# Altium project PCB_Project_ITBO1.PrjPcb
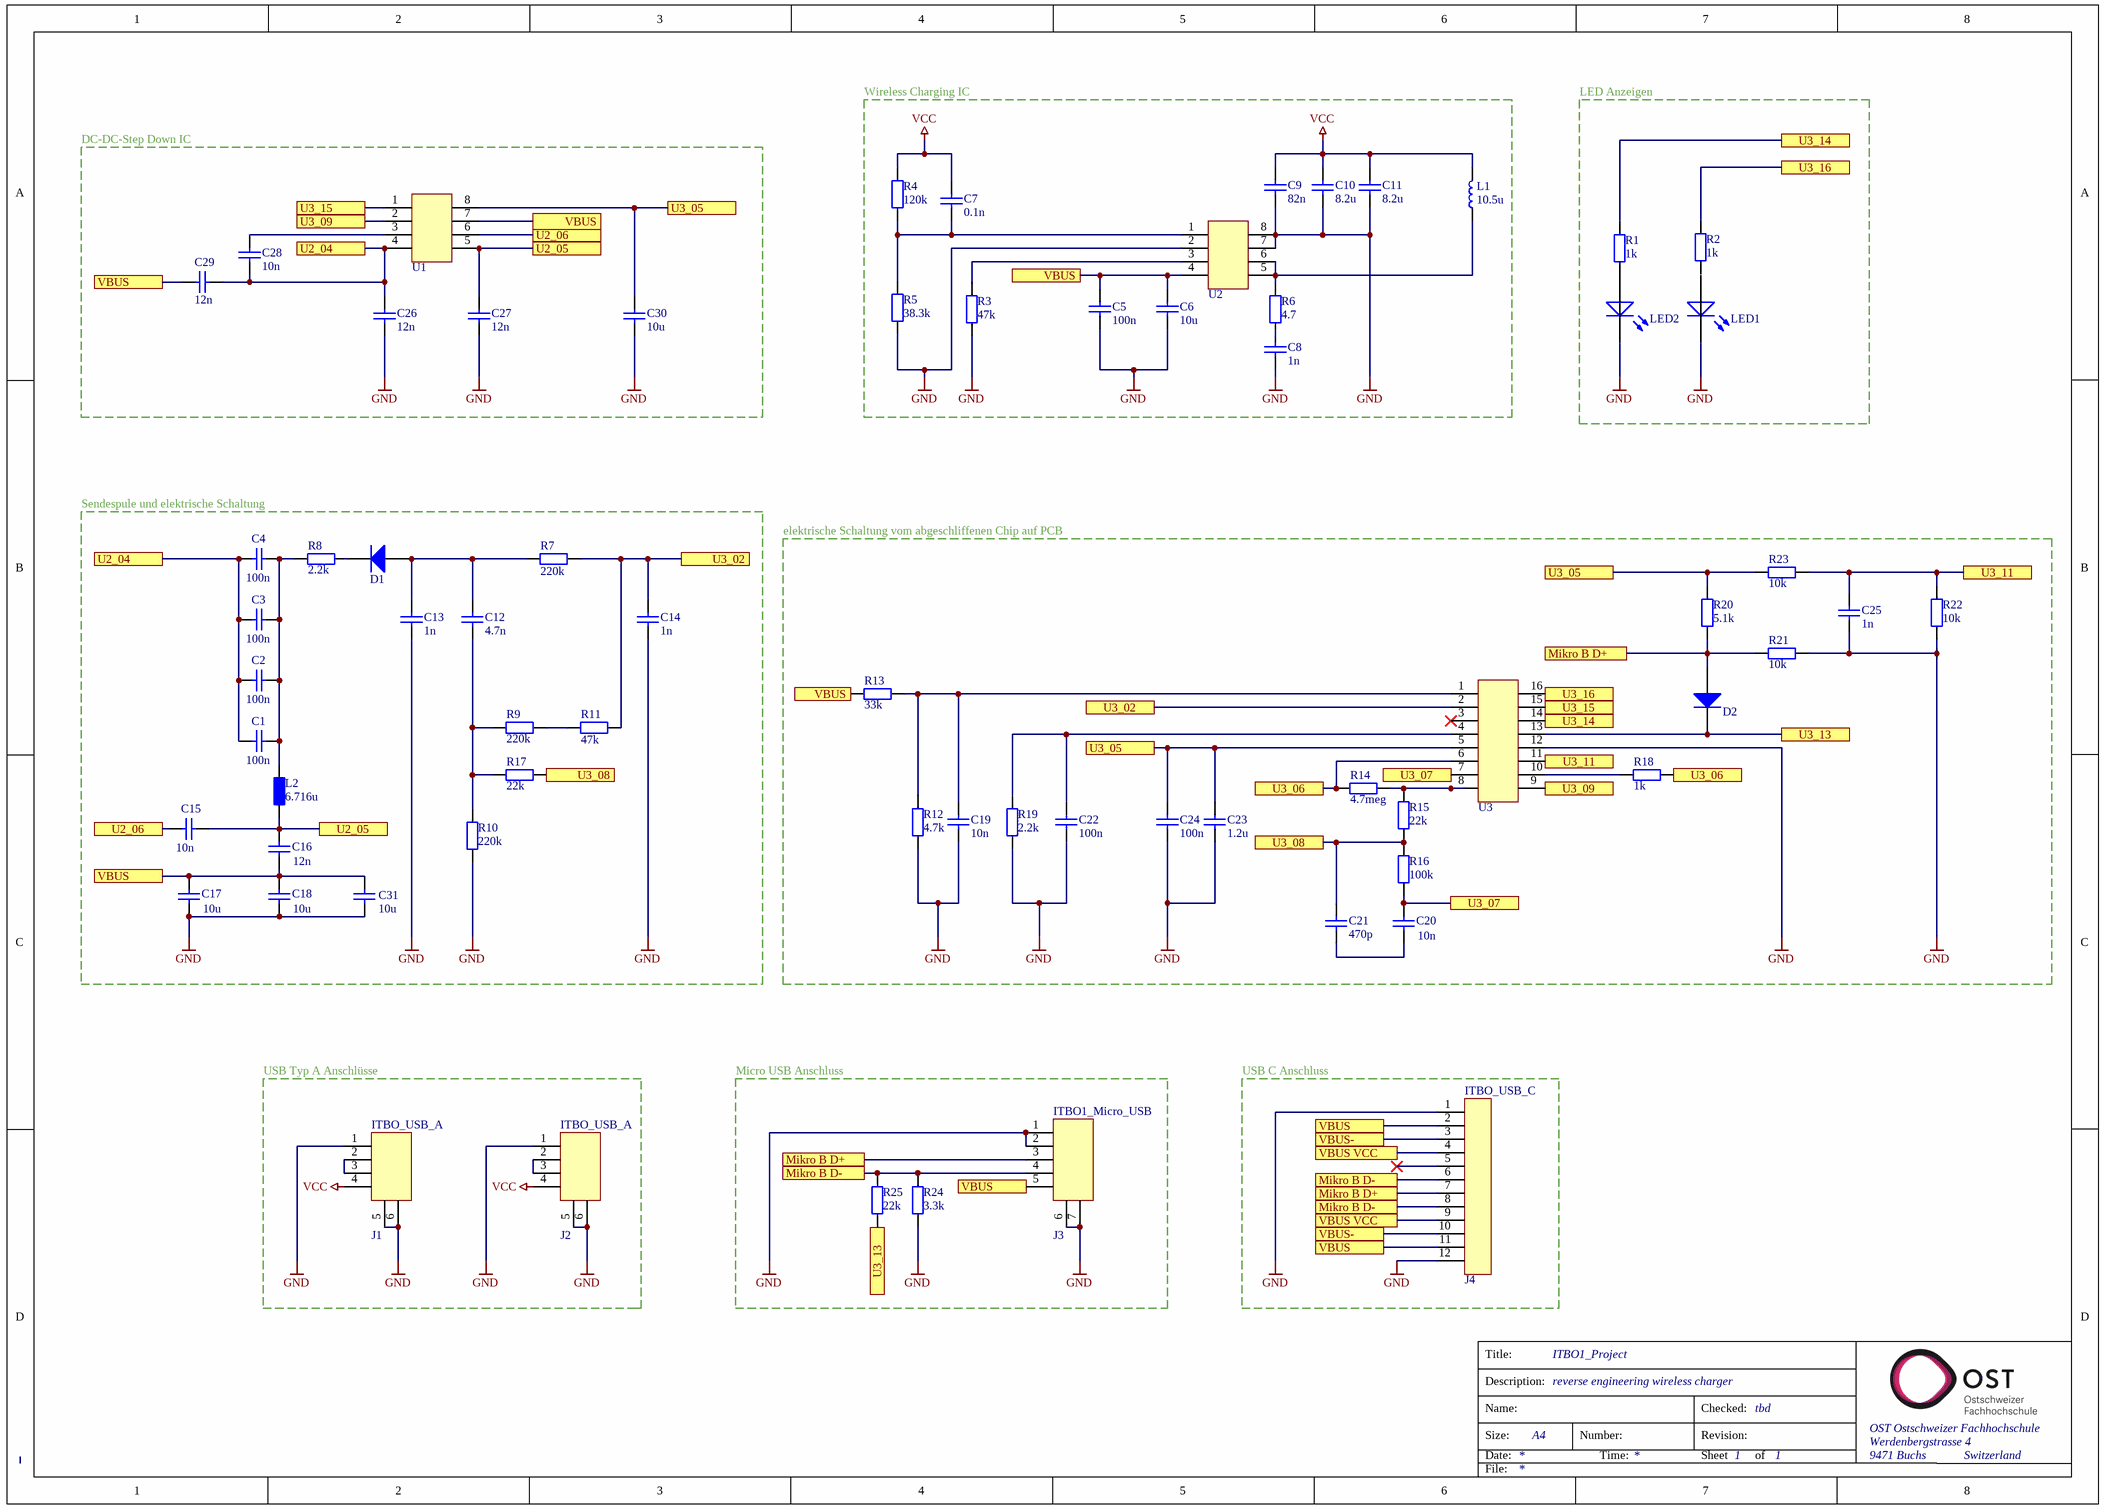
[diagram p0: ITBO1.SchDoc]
prj_author: Leonie Zellweger; prj_number: 1; prj_revision: A2.0
1 sheet, 69 parts. Net scope: flat (ports and power ports of the same name join across sheets).
Board file: ITBO1.PcbDoc

## Sheet ITBO1.SchDoc: ITBO1_Project
size A3; CheckedBy: tbd; Author: Leonie Zellweger; CompanyName: OST; Organization: OST Ostschweizer Fachhochschule; Address1: Werdenbergstrasse 4; Address2: 9471 Buchs; Address3: Switzerland; DocumentNumber: 1; Revision: A2.0; SheetNumber: 1; SheetTotal: 1; Size: A4; ShortDescription: reverse engineering wireless charger; SPICEModelCacheDJXWFJHT: <root> / <DocumentId>DJXWFJHT</DocumentId> / <CacheFrame Number="0"> / <Model Name="bas16" Kind="MDL"> / <Text>*DEVICE=BAS16,D / * BAS16 D model / * created using Parts release 7.1 on 07/27/98 at 15:24 / * Parts is a MicroSim product. / * Downloaded 2006-12-31 NXP / .MODEL BAS16 D / + IS=6.0289E-9 / + N=2.1283 / + RS=1.0000E-3 / + IKF=37.638E-3 / + CJO=593.63E-15 / + M=.1 / + VJ=.68774 / + ISR=2.0646e-9 / + NR=4.9950 / + BV=113.60 / + IBV=10 / + TT=4.5000E-9</Text> / </Model> / </CacheFrame> / </root>

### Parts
C1  100n  [1206]
C2  100n  [1206]
C3  100n  [1206]
C4  100n  [1206]
C5  100n  [0603 - R]
C6  10u  [0603 - R]
C7  0.1n  [0603 - R]
C8  1n  [0603 - R]
C9  82n  [0603 - R]
C10  8.2u  [0805]
C11  8.2u  [0805]
C12  4.7n  [0603 - R]
C13  1n  [0603 - R]
C14  1n  [0603 - R]
C15  10n  [0603 - R]
C16  12n  [0603 - R]
C17  10u  [0805]
C18  10u  [0805]
C19  10n  [0603 - R]
C20  10n  [0603 - R]
C21  470p  [0603 - R]
C22  100n  [0603 - R]
C23  1.2u  [0603 - R]
C24  100n  [0603 - R]
C25  1n  [0603 - R]
C26  12n  [0603 - R]
C27  12n  [0603 - R]
C28  10n  [0603 - R]
C29  12n  [0603 - R]
C30  10u  [0603 - R]
C31  10u  [0805]
D1  1N4148W-7-F  [DIODES_SOD123_2_H]  (value not drawn)
D2  1N4148W-7-F  [DIODES_SOD123_2_H]  (value not drawn)
J1  ITBO_USB_A
J2  ITBO_USB_A
J3  ITBO1_Micro_USB
J4  ITBO_USB_C
L1  10.5u
L2  value 6.716u  (hidden comment: L)
LED1  tbd  (value not drawn)
LED2  tbd  (value not drawn)
R1  value 1k  [0603 - R]  (hidden comment: 4.7)
R2  value 1k  [0603 - R]  (hidden comment: 4.7)
R3  47k  [0603 - R]
R4  120k  [0603 - R]
R5  38.3k  [0603 - R]
R6  4.7  [0603 - R]
R7  220k  [0603 - R]
R8  2.2k  [0603 - R]
R9  220k  [0603 - R]
R10  220k  [0603 - R]
R11  47k  [0603 - R]
R12  4.7k  [0603 - R]
R13  33k  [0603 - R]
R14  4.7meg  [0603 - R]
R15  22k  [0603 - R]
R16  100k  [0603 - R]
R17  22k  [0603 - R]
R18  1k  [0603 - R]
R19  2.2k  [0603 - R]
R20  5.1k  [0603 - R]
R21  10k  [0603 - R]
R22  10k  [0603 - R]
R23  10k  [0603 - R]
R24  3.3k  [0603 - R]
R25  22k  [0603 - R]
U1  ITBO1_U2  (value not drawn)
U2  ITBO1_U1  (value not drawn)
U3  ITBO1_U3  (value not drawn)

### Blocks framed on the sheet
Wireless Charging IC: C5-C11 L1 R3-R6 U2
LED Anzeigen: LED1 LED2 R1 R2
DC-DC-Step Down IC: C26-C30 U1
Sendespule und elektrische Schaltung: C1-C4 C12-C18 C31 D1 L2 R7-R11 R17
elektrische Schaltung vom abgeschliffenen Chip auf PCB: C19-C25 D2 R12-R16 R18-R23 U3
Micro USB Anschluss: J3 R24 R25
USB C Anschluss: J4

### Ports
Mikro B D+, Mikro B D-, U2_04, U2_05, U2_06, U3_02, U3_05, U3_06, U3_07, U3_08, U3_09, U3_11, U3_13, U3_14, U3_15, U3_16, VBUS, VBUS VCC, VBUS-

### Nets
GND: C5.1 C6.1 C8.1 C9.1 C10.1 C11.1 C13.1 C14.1 C17.1 C18.1 C19.2 C22.2 C23.1 C24.1 C25.1 C26.1 C27.1 C30.2 C31.1 J1.1 J1.5 J1.6 J2.1 J2.5 J2.6 J3.1 J3.2 J3.6 J3.7 J4.1 J4.12 LED1.1(K) LED2.1(K) R3.1 R5.1 R10.1 R12.2 R19.2 R21.2 R22.1 R24.1 U2.2 U2.7 U2.8 U3.12
VCC: C7.2 C9.2 C10.2 C11.2 J1.4 J2.4 L1.2 R4.2
NetC1_1: C1.1 C2.1 C3.1 C4.1 L2.2 R8.1
NetC1_2: C1.2 C2.2 C3.2 C4.2 C26.2 C28.1 C29.2 U1.4 ; port U2_04
NetC5_2: C5.2 C6.2 C16.2 C17.2 C18.2 C29.1 C31.2 J3.5 J4.2 J4.11 R13.2 U1.7 U2.4 ; port VBUS
NetC7_1: C7.1 R4.1 R5.2 U2.1
NetC8_2: C8.2 R6.1
NetC12_1: C12.1 R9.1 R10.2 R17.2
NetC12_2: C12.2 C13.2 D1.2(A) R7.2
NetC14_2: C14.2 R7.1 R11.2 U3.2 ; port U3_02
NetC15_1: C15.1 C16.1 C27.2 L2.1 U1.5 ; port U2_05
NetC15_2: C15.2 U1.6 ; port U2_06
NetC19_1: C19.1 R12.1 R13.1 U3.1
NetC20_1: C20.1 C21.1
NetC20_2: C20.2 R16.1 U3.7 ; port U3_07
NetC21_2: C21.2 R15.1 R16.2 R17.1 ; port U3_08
NetC22_1: C22.1 R19.1 U3.4
NetC23_2: C23.2 C24.2 C30.1 R20.2 R23.2 U1.8 U3.5 ; port U3_05
NetC25_2: C25.2 R22.2 R23.1 U3.11 ; port U3_11
NetC28_2: C28.2 U1.3
NetD1_1: D1.1(K) R8.2
NetD2_1: D2.1(K) R25.1 U3.13 ; port U3_13
NetD2_2: D2.2(A) J3.3 J4.7 R20.1 R21.1 ; port Mikro B D+
NetJ1_2: J1.2 J1.3
NetJ2_2: J2.2 J2.3
NetJ3_4: J3.4 J4.6 J4.8 R24.2 R25.2 ; port Mikro B D-
NetJ4_3: J4.3 J4.10 ; port VBUS-
NetJ4_4: J4.4 J4.9 ; port VBUS VCC
NetL1_1: L1.1 R6.2 U2.5 U2.6
NetLED2_2: LED2.2(A) R1.2
NetR1_1: R1.1 U3.14 ; port U3_14
NetR2_1: R2.1 U3.16 ; port U3_16
NetR3_2: R3.2 U2.3
NetR9_2: R9.2 R11.1
NetR14_1: R14.1 R18.2 U3.6 ; port U3_06
NetR14_2: R14.2 R15.2 U3.8
NetR18_1: R18.1 U3.10
NetU1_1: U1.1 U3.15 ; port U3_15
NetU1_2: U1.2 U3.9 ; port U3_09

Not connected (* = marked no-connect by the designer): J4 5*; LED1 2(A); R2 2; U3 3*

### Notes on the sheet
- USB Typ A Anschlüsse

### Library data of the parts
C1-C31 = C: Capacitor; #Manufacturer: Generic Components; #Publisher: Dr. A. Heinzelmann; #Class: Passive; Initial Voltage: 0V
D1 D2 = 10707_EuR1_Team06-0009-A.1: Fast Switching Diode, 100 V, 2 A, 300 mA; Manufacturer: Diodes Incorporated
L1 = L - Power: Inductor - Power; #Manufacturer: Generic Components; #Publisher: Dr. A. Heinzelmann; #Class: Passive; #ClassSub: Resistor
L2 = L: Inductor; #Manufacturer: Generic Components; #Publisher: Dr. A. Heinzelmann; #Class: Passive; #ClassSub: Resistor
LED1 = LED red: Manufacturer: generic; #ClassSub: LEDs; #Class: Generic-Components
LED2 = LED blue: Manufacturer: generic; #ClassSub: LEDs; #Class: Generic-Components
R1-R25 = R: Resistor; #Manufacturer: Generic Components; #Publisher: Dr. A. Heinzelmann; #Class: Passive
U1 = ITBO1_U2: T2282L
U2 = ITBO1_U1: PN7724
